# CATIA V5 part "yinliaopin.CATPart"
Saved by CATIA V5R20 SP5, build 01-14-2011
Part number: Part1
Material "China Blue": density 7860 kg/m3, Young's modulus 2e+11 Pa, Poisson ratio 0.266
Bounding box of the stored display mesh (mm): x -25 to 25, y -25 to 25.2, z -1 to 110
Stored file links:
  E:\180212218\yinliaopin.CATPart
  C:\Program Files\Dassault Systemes\B20\intel_a\startup\materials\Catalog.CATMaterial
  C:\Program Files\Dassault Systemes\B20\intel_a\startup\materials\sunset.jpg
  C:\Program Files\Dassault Systemes\B20\intel_a\startup\materials\yellow_env_512x512.jpg
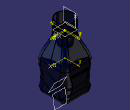
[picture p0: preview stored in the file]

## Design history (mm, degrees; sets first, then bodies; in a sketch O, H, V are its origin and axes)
Set1
  Sketch1 on face of Pad1 from Sketch3.L1, origin (25, 0, 0), H (0, 1, 0), V (0, 0, 1)
    spline S1 through (-40, 10) (-10, 20) (10, 10) (30, 20)
  Extrude1: Element1 Sketch1, Lim1 66, Lim2 66
  MultiSel1: CommonCtxFeats ({extract ExtractElem face of Fillet1}; {extract ExtractElem face of Pad1 from Sketch3.L1}; {extract ExtractElem face of Fillet1}; {extract ExtractElem face of Pad1 from Sketch3.L4}; {extract ExtractElem face of Fillet1}; {extract ExtractElem face of Pad1 from Sketch3.L3}; {extract ExtractElem face of Fillet1}; {extract ExtractElem face of Pad1 from Sketch3.L2})
  Sketch2 on face of Pad1 from Sketch3.L3, origin (-25, 0, 0), H (0, -1, 0), V (0, 0, 1)
    spline S1 through (-40, 20) (-10, 30) (10, 40) (30, 40)
  Extrude2: Element1 Sketch2, Lim1 66, Lim2 66
  MultiSel2: CommonCtxFeats ({extract ExtractElem face of Fillet1}; {extract ExtractElem face of Pad1 from Sketch3.L2}; {extract ExtractElem face of Fillet1}; {extract ExtractElem face of Pad1 from Sketch3.L1}; {extract ExtractElem face of Fillet1}; {extract ExtractElem face of Pad1 from Sketch3.L4}; {extract ExtractElem face of Fillet1}; {extract ExtractElem face of Pad1 from Sketch3.L3})
  Join1: Elements ({intersect ToIntersect1 {extract ExtractElem face of Fillet1}, ToIntersect2 Extrude2}; {intersect ToIntersect1 {extract ExtractElem face of Pad1 from Sketch3.L2}, ToIntersect2 Extrude2}; {intersect ToIntersect1 {extract ExtractElem face of Fillet1}, ToIntersect2 Extrude2}; {intersect ToIntersect1 {extract ExtractElem face of Pad1 from Sketch3.L1}, ToIntersect2 Extrude2}; {intersect ToIntersect1 {extract ExtractElem face of Fillet1}, ToIntersect2 Extrude2}; {intersect ToIntersect1 {extract ExtractElem face of Pad1 from Sketch3.L4}, ToIntersect2 Extrude2}; {intersect ToIntersect1 {extract ExtractElem face of Fillet1}, ToIntersect2 Extrude2}; {intersect ToIntersect1 {extract ExtractElem face of Pad1 from Sketch3.L3}, ToIntersect2 Extrude2})
  Join2: Elements ({intersect ToIntersect1 {extract ExtractElem face of Fillet1}, ToIntersect2 Extrude1}; {intersect ToIntersect1 {extract ExtractElem face of Pad1 from Sketch3.L1}, ToIntersect2 Extrude1}; {intersect ToIntersect1 {extract ExtractElem face of Fillet1}, ToIntersect2 Extrude1}; {intersect ToIntersect1 {extract ExtractElem face of Pad1 from Sketch3.L4}, ToIntersect2 Extrude1}; {intersect ToIntersect1 {extract ExtractElem face of Fillet1}, ToIntersect2 Extrude1}; {intersect ToIntersect1 {extract ExtractElem face of Pad1 from Sketch3.L3}, ToIntersect2 Extrude1}; {intersect ToIntersect1 {extract ExtractElem face of Fillet1}, ToIntersect2 Extrude1}; {intersect ToIntersect1 {extract ExtractElem face of Pad1 from Sketch3.L2}, ToIntersect2 Extrude1})
  Plane1: type Normal, Curve Join1, RefPoint vertex [face of MultiSel2 | face of MultiSel2]
  Circle1: type CtrRad, Start 0, End 180, Center vertex [face of MultiSel2 | face of MultiSel2], Support Plane1, Radius 1, FirstDirection (1, 0, 0)
  Plane2: type Normal, Curve Join2, RefPoint vertex [face of MultiSel1 | face of MultiSel1]
  Circle2: type CtrRad, Start 0, End 180, Center vertex [face of MultiSel1 | face of MultiSel1], Support Plane2, Radius 1, FirstDirection (1, 0, 0)
Body1 (main body), material "China Blue"
  Set2
    Sketch3 on xy-plane, origin (0, 0, 0), H (1, 0, 0), V (0, 1, 0)
      line L1 (25, 25) -> (25, -25)
      line L2 (25, -25) -> (-25, -25)
      line L3 (-25, -25) -> (-25, 25)
      line L4 (-25, 25) -> (25, 25)
      distance L2 L4 = 50
      distance L1 L3 = 50
      vertical: L1 V, L3 V
      horizontal: L2 H, L4 H
      equidistance: L1 L3 O, L2 L4 O
  Pad1: profile Sketch3, direction (0, 0, 1), length 50
  Fillet1: on edge [face of Pad1 from Sketch3.L2 | face of Pad1 from Sketch3.L3]; edge [face of Pad1 from Sketch3.L4 | face of Pad1 from Sketch3.L1]; edge [face of Pad1 from Sketch3.L3 | face of Pad1 from Sketch3.L4]; edge [face of Pad1 from Sketch3.L1 | face of Pad1 from Sketch3.L2]
  Fillet2: on edge [start face of Pad1 | face of Pad1 from Sketch3.L4]
  Plane3: type Offset, RefPlane end face of Pad1, Offset 40, reversed
  Sketch4 on Plane3, origin (0, 0, 90), H (1, 0, 0), V (0, -1, 0)
    circle A1 centre (0, 0) radius 15
    radius A1 = 15
  Pad2: profile Sketch4, direction (0, 0, -1), length -20
  Sketch5 on end face of Pad1, origin (0, 0, 50), H (1, 0, 0), V (0, 1, 0)
    point P1 (25, 0)
    distance V P1 = 25
    coincidence: P1 H
  Sketch6 on start face of Pad2, origin (0, 0, 90), H (1, 0, 0), V (0, -1, 0)
    point P1 (15, 0)
    distance P1 V = 15
    coincidence: P1 H
  Loft1: solid, Sections ({boundary Boundary {extract ExtractElem end face of Pad1}}; {boundary Boundary {extract ExtractElem start face of Pad2}}), StartFace end face of Pad1, EndFace start face of Pad2
  Slot1: profile Circle1, centre curve Join1
  Slot2: profile Circle2, centre curve Join2
  Shell1: ExtOffset 0, Face end face of Pad2, IntOffset 1
  Sketch7 on {extract ExtractElem start face of Pad2}, origin (0, 0, 90), H (1, 0, 0), V (0, 1, 0)
    point P1 (15, 0)
    distance P1 V = 15
    coincidence: P1 H
  Plane4: type Offset, RefPlane {extract ExtractElem start face of Pad2}, Offset 2
  Sketch8 on Plane4, origin (0, 0, 92), H (1, 0, 0), V (0, 1, 0)
    point P1 (15, 0)
    distance P1 V = 15
    coincidence: P1 H
  Helix1: Direction Z axis, RefPoint Sketch8, Pitch 2, Height 15, TaperAngle 0
  Point1: type OnCurve, Support Helix1, RefPoint vertex of Helix1, Length -3.889
  Line1: type PtDir, RefPoint vertex of Helix1, Direction (1, 0, 0), Start 0, End 7
  Connect1: Curve1 Helix1, Point1 Point1, Tension1 1, Curve2 Line1, Point2 vertex of Line1, Tension2 1
  Line2: type PtDir, RefPoint Sketch8, Direction (1, 0, 0), Start 0, End -7
  Point2: type OnCurve, Support Connect1, Length 5.227
  Connect2: Curve1 Line2, Point1 vertex of Line2, Tension1 1, Curve2 Connect1, Point2 Point2, Tension2 1
  Plane5: type Normal, Curve Connect2, RefPoint vertex of Connect1
  Sketch9 on Plane5, origin (-8, 0, 0), H (0, 1, 0), V (0, 0, 1)
    circle A1 centre (0, 107.0454) radius 0.5
    point P1 (0, 107.0454)
    coincidence: P1 V
  Rib1: profile Sketch9, centre curve Connect2
  Body2
    Sketch10 on face of Pad1 from Sketch3.L4, origin (0, 25, 0), H (-1, 0, 0), V (0, 0, 1)
      polyline C1
      polyline C2
      polyline C3
      polyline C4
      polyline C5
      polyline C6
      polyline C7
      polyline C8
      polyline C9
      polyline C10
      polyline C11
    Sketch11 on {extract ExtractElem start face of Pad2}, origin (0, 0, 90), H (1, 0, 0), V (0, 1, 0)
      circle A1 centre (0, 0) radius 14
      radius A1 = 14
    Pad3: profile Sketch11, direction (0, 0, 1), length 20
  Remove1: tool Body2
  Pad4: profile Sketch10, direction (0, 1, 0), length 0.2
  Sketch12 on start face of Pad1, origin (0, 0, 0), H (1, 0, 0), V (0, -1, 0)
    point P1 (0, 0)
    construction line L1 through (0, 0) direction (1, 0)
    construction line L2 through (0, 0) direction (0, 1)
    polyline C1
    polyline C2
    polyline C3
    polyline C4
  Pad5: profile Sketch12, direction (0, 0, -1), length 1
